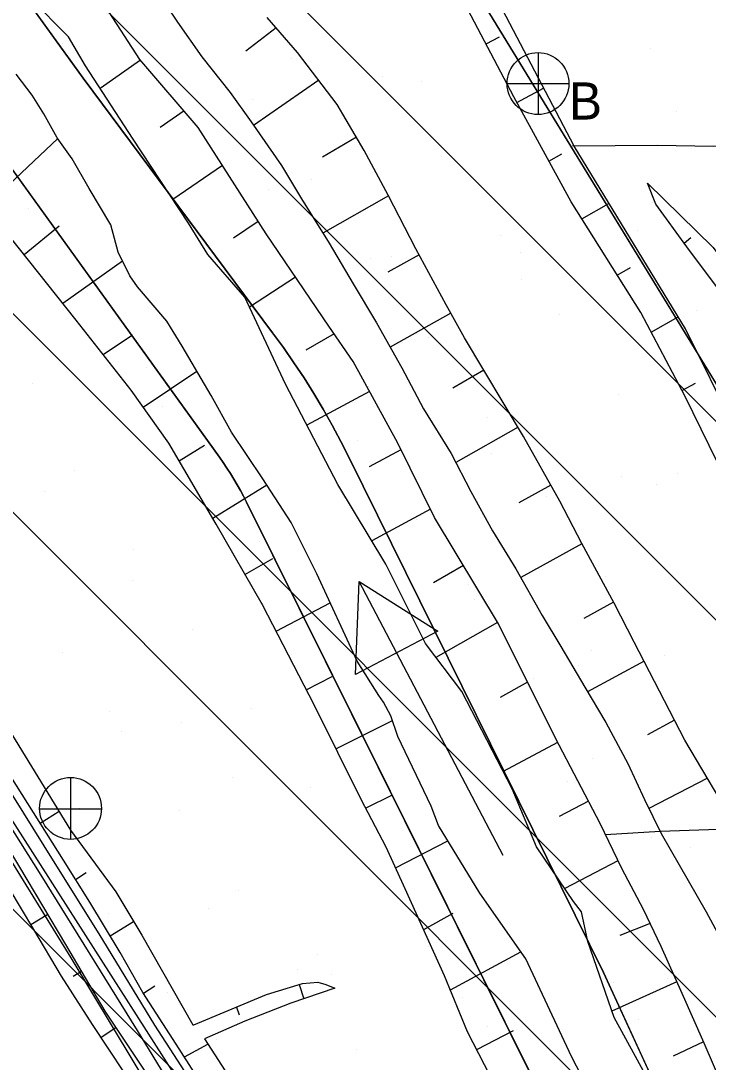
# Model space of a CAD drawing. Extents: x 417995 to 421451, y 4454518 to 4458015.
# Drawn here: x 421031.2 to 421108.9, y 4456083.1 to 4456200.9 of the extents above; entities that cross this region are included whole.
import ezdxf

# ---------------------------------------------------------------- set-up
doc = ezdxf.new("R2010")
doc.units = 0
for name, color, linetype in [('ADAKENARI', 7, 'Continuous'), ('Default', 7, 'Continuous'), ('Hid_Dere_Sulu_Yat_Gen', 7, 'Continuous'), ('PL_AYA_BOLGE_PARKI', 7, 'Continuous'), ('PL_AYA_PARK_DINLENME', 7, 'Continuous'), ('PL_TA_K_DERE', 7, 'Continuous'), ('S_Istikamet_Oku', 7, 'Continuous'), ('S_Rogar_Kapagi', 7, 'Continuous'), ('S_Rogar_Kapagi_Buski', 7, 'Continuous'), ('Sev_Sevalti', 7, 'Continuous'), ('Sev_Sevustu', 7, 'Continuous'), ('Sev_Tarama', 7, 'Continuous'), ('Sinir_itirazli_Mulkiyet', 7, 'Continuous'), ('Sinir_Tel_bir_taraf', 7, 'Continuous'), ('SN_TR_SIVILASMA', 7, 'Continuous'), ('TR_PARKALANI', 7, 'Continuous'), ('Yol_Toprak_Duz', 7, 'Continuous'), ('Yol_Toprak_Kesik', 7, 'Continuous')]:
    doc.layers.add(name, color=color, linetype=linetype)

# ---------------------------------------------------------------- blocks, each defined once
blk = doc.blocks.new('POINT_DISPLAY')
at = {"layer": 'Default'}
blk.add_line((0, 0), (0, 0), dxfattribs=at)

msp = doc.modelspace()

# ---------------------------------------------------------------- linework, layer by layer
at = {"layer": 'ADAKENARI'}
for p, q in [((420917.7, 4456473.63), (421125.1, 4456134.88)), ((421053.63, 4456151.54), (420943.98, 4456303.65)), ((420959.73, 4456303.08), (421038.21, 4456194.41)), ((421080.66, 4456031.58), (420960.94, 4456218.7)), ((421038.21, 4456194.41), (421059.65, 4456165.62)), ((421059.65, 4456165.62), (421060.87, 4456163.94)), ((421060.87, 4456163.94), (421062.06, 4456162.23)), ((421062.06, 4456162.23), (421063.2, 4456160.5)), ((421063.2, 4456160.5), (421064.3, 4456158.74)), ((421064.3, 4456158.74), (421065.37, 4456156.96)), ((421065.37, 4456156.96), (421066.39, 4456155.15)), ((421066.39, 4456155.15), (421067.37, 4456153.32)), ((421067.37, 4456153.32), (421068.32, 4456151.47)), ((421054.06, 4456150.93), (421053.63, 4456151.54)), ((421068.32, 4456151.47), (421097.08, 4456093.28)), ((421054.47, 4456150.32), (421054.06, 4456150.93)), ((421054.87, 4456149.69), (421054.47, 4456150.32)), ((421055.26, 4456149.06), (421054.87, 4456149.69)), ((421055.64, 4456148.42), (421055.26, 4456149.06)), ((421056, 4456147.78), (421055.64, 4456148.42)), ((421056.35, 4456147.12), (421056, 4456147.78)), ((421056.69, 4456146.46), (421056.35, 4456147.12)), ((421128.16, 4456002.78), (421056.69, 4456146.46)), ((421097.08, 4456093.28), (421123.49, 4456035.93))]:
    msp.add_line(p, q, dxfattribs=at)
at = {"layer": 'Hid_Dere_Sulu_Yat_Gen'}
for points in [[(421103.34, 4456078.94), (421098.27, 4456088.18), (421095.3, 4456096.78), (421094.59, 4456100.15), (421093.69, 4456101.29), (421089.5, 4456107.48), (421086.74, 4456114.05), (421081.05, 4456125.03), (421076.93, 4456130.47), (421072.47, 4456139.45), (421067.01, 4456148.44), (421061.1, 4456159.81), (421056.49, 4456169.64), (421052.33, 4456174.45), (421050.13, 4456177.99), (421043.78, 4456187.61), (421038.47, 4456195.8), (421036.55, 4456199.07), (421032.24, 4456203.5)], [(421097.4, 4456076.13), (421093.46, 4456083.78), (421088.28, 4456094.82), (421083.09, 4456102.26), (421078.42, 4456109.88), (421077.59, 4456112.07), (421073.82, 4456119.95), (421073.04, 4456122.28), (421072.21, 4456123.86), (421071.67, 4456124.59), (421069.22, 4456128.46), (421064.64, 4456138.34), (421061.73, 4456144.15), (421058.54, 4456149.11), (421054.99, 4456154.39), (421052.69, 4456158.5), (421049.42, 4456164.09), (421047.67, 4456166.91), (421044.35, 4456170.81), (421043.49, 4456172.05), (421042.19, 4456174.73), (421041.34, 4456177.81), (421038.91, 4456181.92), (421036.96, 4456185.27), (421035.28, 4456187.65), (421033.75, 4456190.36), (421032.44, 4456192.47), (421030.65, 4456194.86)]]:
    msp.add_lwpolyline(points, dxfattribs=at)
at = {"layer": 'PL_AYA_BOLGE_PARKI'}
msp.add_lwpolyline([(420862.75, 4456551.08), (420917.7, 4456473.63), (421125.1, 4456134.88)], dxfattribs=at)
at = {"layer": 'PL_AYA_PARK_DINLENME'}
for points in [[(421088.01, 4455998.87), (421080.33, 4456015.32), (421072.31, 4456031.61), (421063.94, 4456047.72), (421055.24, 4456063.65), (421046.21, 4456079.4), (421036.85, 4456094.95), (421036.85, 4456094.94), (420796.81, 4456484.25)], [(420917.7, 4456473.63), (421125.1, 4456134.88), (421134.31, 4456119.44), (421143.18, 4456103.81), (421151.7, 4456087.99), (421159.87, 4456071.98), (421167.68, 4456055.79), (421175.13, 4456039.43), (421182.22, 4456022.92), (421188.93, 4456006.25), (421195.28, 4455989.43)], [(420943.98, 4456303.65), (421053.63, 4456151.54), (421054.06, 4456150.93), (421054.47, 4456150.32), (421054.87, 4456149.69), (421055.26, 4456149.06), (421055.64, 4456148.42), (421056, 4456147.78), (421056.35, 4456147.12), (421056.69, 4456146.46), (421128.16, 4456002.78), (421151.46, 4455956.18)], [(421152.17, 4455978.57), (421123.49, 4456035.93), (421097.08, 4456093.28), (421068.32, 4456151.47), (421067.37, 4456153.32), (421066.39, 4456155.15), (421065.37, 4456156.96), (421064.3, 4456158.74), (421063.2, 4456160.5), (421062.06, 4456162.23), (421060.87, 4456163.94), (421059.65, 4456165.62), (421038.21, 4456194.41), (420959.73, 4456303.08)]]:
    msp.add_lwpolyline(points, dxfattribs=at)
at = {"layer": 'PL_TA_K_DERE'}
for points in [[(420943.98, 4456303.65), (421053.63, 4456151.54), (421054.06, 4456150.93), (421054.47, 4456150.32), (421054.87, 4456149.69), (421055.26, 4456149.06), (421055.64, 4456148.42), (421056, 4456147.78), (421056.35, 4456147.12), (421056.69, 4456146.46), (421128.16, 4456002.78), (421151.46, 4455956.18)], [(421152.17, 4455978.57), (421123.49, 4456035.93), (421097.08, 4456093.28), (421068.32, 4456151.47), (421067.37, 4456153.32), (421066.39, 4456155.15), (421065.37, 4456156.96), (421064.3, 4456158.74), (421063.2, 4456160.5), (421062.06, 4456162.23), (421060.87, 4456163.94), (421059.65, 4456165.62), (421038.21, 4456194.41), (420959.73, 4456303.08)]]:
    msp.add_lwpolyline(points, dxfattribs=at)
at = {"layer": 'S_Istikamet_Oku'}
for p, q in [((421069.03, 4456126.97), (421069.44, 4456137.47)), ((421085.73, 4456106.49), (421069.44, 4456137.47)), ((421069.44, 4456137.47), (421078.33, 4456131.86)), ((421078.33, 4456131.86), (421069.03, 4456126.97)), ((421078.13, 4456131.99), (421078.13, 4456131.99)), ((421078.13, 4456131.99), (421078.13, 4456131.99))]:
    msp.add_line(p, q, dxfattribs=at)
at = {"layer": 'S_Rogar_Kapagi'}
for p, q in [((421036.84, 4456108.31), (421036.84, 4456115.31)), ((421033.27, 4456111.77), (421040.27, 4456111.77))]:
    msp.add_line(p, q, dxfattribs=at)
msp.add_circle((421036.79, 4456111.83), 3.5, dxfattribs=at)
at = {"layer": 'S_Rogar_Kapagi_Buski'}
for p, q in [((421089.67, 4456197.29), (421089.67, 4456190.29)), ((421086.17, 4456193.79), (421093.17, 4456193.79))]:
    msp.add_line(p, q, dxfattribs=at)
msp.add_circle((421089.67, 4456193.79), 3.5, dxfattribs=at)
at = {"layer": 'Sev_Sevalti'}
for points in [[(421187.5, 4456114.49), (421152.1, 4456115.65), (421136.4, 4456115.89), (421133.91, 4456116.58), (421128.87, 4456123.93), (421123.11, 4456135.15), (421117.67, 4456144.85), (421111.98, 4456154.75), (421106.35, 4456166.06), (421093.76, 4456186.7), (421085.26, 4456202.89), (421080.76, 4456211.67), (421071.96, 4456227.21), (421061.34, 4456243.49), (421051.89, 4456256.28), (421041.66, 4456272.25), (421035.99, 4456281.59), (421027.71, 4456295.81), (421022.87, 4456306.93)], [(421046.26, 4456204.69), (421048.89, 4456200.72), (421051.63, 4456196.81), (421054.85, 4456192.76), (421057.22, 4456189.45), (421060.65, 4456184.54), (421062.93, 4456180.74), (421066.03, 4456175.73), (421068.76, 4456171.16), (421071.41, 4456166.73), (421074.28, 4456161.65), (421076.73, 4456157), (421079.84, 4456151.95), (421082.06, 4456147.65), (421084.51, 4456143.23), (421087.18, 4456138.9), (421090.14, 4456133.64), (421092.24, 4456130.12), (421094.96, 4456125.53), (421097.33, 4456121.54), (421099.82, 4456116.9), (421101.7, 4456112.85), (421103.59, 4456109.01), (421108.71, 4456100.12), (421112.96, 4456092.25)], [(421103.34, 4456078.94), (421098.27, 4456088.18), (421095.3, 4456096.78), (421094.59, 4456100.15), (421093.69, 4456101.29), (421089.5, 4456107.48), (421086.74, 4456114.05), (421081.05, 4456125.03), (421076.93, 4456130.47), (421072.47, 4456139.45), (421067.01, 4456148.44), (421061.1, 4456159.81), (421056.49, 4456169.64), (421052.33, 4456174.45), (421050.13, 4456177.99), (421043.78, 4456187.61), (421038.47, 4456195.8), (421036.55, 4456199.07), (421032.24, 4456203.5)], [(420981.53, 4456200.82), (420985.46, 4456194.46), (420989.57, 4456187.63), (420993.82, 4456179.59), (420997.48, 4456172.93), (421001.69, 4456166.45), (421005.49, 4456160.76), (421012.87, 4456149.79), (421016.12, 4456143.59), (421021.62, 4456134.26), (421027.94, 4456123.77), (421036.8, 4456109.38), (421041.9, 4456102.38), (421044.85, 4456097.48), (421050.63, 4456087.34)], [(421097.4, 4456076.13), (421093.46, 4456083.78), (421088.28, 4456094.82), (421083.09, 4456102.26), (421078.42, 4456109.88), (421077.59, 4456112.07), (421073.82, 4456119.95), (421073.04, 4456122.28), (421072.21, 4456123.86), (421071.67, 4456124.59), (421069.22, 4456128.46), (421064.64, 4456138.34), (421061.73, 4456144.15), (421058.54, 4456149.11), (421054.99, 4456154.39), (421052.69, 4456158.5), (421049.42, 4456164.09), (421047.67, 4456166.91), (421044.35, 4456170.81), (421043.49, 4456172.05), (421042.19, 4456174.73), (421041.34, 4456177.81), (421038.91, 4456181.92), (421036.96, 4456185.27), (421035.28, 4456187.65), (421033.75, 4456190.36), (421032.44, 4456192.47), (421030.65, 4456194.86)], [(421102.05, 4456182.51), (421109.49, 4456175.24), (421116.81, 4456165.26), (421123.12, 4456156.98), (421127.12, 4456148.55), (421131.6, 4456138.36), (421135.06, 4456129.81), (421137.23, 4456124.28), (421137.65, 4456121.8), (421137.29, 4456119.54)], [(421044.67, 4456079.27), (421039.28, 4456087.4), (421035.76, 4456092.85), (421032.63, 4456098.13), (421029.86, 4456102.8), (421024.55, 4456111.54), (421021.32, 4456117.19), (421017.79, 4456122.38), (421015.33, 4456126.41), (421012.17, 4456131.8), (421009.28, 4456136.48), (421006.12, 4456141.71), (421002.42, 4456146.74), (420999.46, 4456151.32), (420996.31, 4456156.29), (420993.34, 4456160.43), (420990.9, 4456164.01), (420989.26, 4456167.55), (420988.12, 4456170.4), (420988.01, 4456173.95)], [(421066.69, 4456091.51), (421061.7, 4456089.79), (421056.49, 4456087.76), (421051.94, 4456085.79), (421060.47, 4456072.59), (421065.96, 4456061.83), (421071.99, 4456051.11), (421077.47, 4456041.76), (421080.94, 4456036.49), (421083.95, 4456030.97), (421087.02, 4456024.17), (421089.21, 4456019.52), (421091.82, 4456013.25), (421094.71, 4456007.22), (421097.85, 4456000.22)]]:
    msp.add_lwpolyline(points, dxfattribs=at)
at = {"layer": 'Sev_Sevustu'}
for points in [[(421204.78, 4456110.51), (421178.81, 4456110.45), (421142.69, 4456111.53), (421132.67, 4456112.57), (421129.35, 4456114.57), (421124.09, 4456123.04), (421119.43, 4456131.97), (421113.53, 4456143.71), (421106.31, 4456158.4), (421101.3, 4456167.9), (421093.41, 4456180.42), (421086.92, 4456192.3), (421079.18, 4456207.06), (421074.43, 4456214.66), (421067.21, 4456226.87), (421052.29, 4456249.7), (421039.34, 4456268.38), (421028.21, 4456288.78), (421016.29, 4456308.87)], [(421111.41, 4456078.46), (421108.48, 4456085.27), (421105.97, 4456090.91), (421103.61, 4456096.23), (421101.6, 4456100.4), (421099.14, 4456105.02), (421096.69, 4456110.11), (421091.64, 4456119.76), (421085.2, 4456132.69), (421077.97, 4456144.74), (421073.8, 4456153.14), (421068.77, 4456162.35), (421066, 4456166.36), (421058.91, 4456176.79), (421051.23, 4456188.83), (421044.62, 4456196.52), (421039.43, 4456204.59)], [(421086.19, 4456077.85), (421081.71, 4456086.57), (421079.11, 4456092.9), (421074.66, 4456102.72), (421072.49, 4456107.45), (421069.67, 4456112.83), (421064.37, 4456123.46), (421058.5, 4456134.84), (421053.27, 4456143.98), (421047.92, 4456153.11), (421043.64, 4456159.11), (421037.44, 4456167.05), (421029.85, 4456176.56), (421023.05, 4456185.41), (421017.09, 4456193.75), (421011.16, 4456201.55)], [(421128.64, 4456079.86), (421124.91, 4456085.93), (421122.05, 4456091.5), (421119.64, 4456096.7), (421116.83, 4456101.25), (421112.26, 4456109.45), (421106.28, 4456119.54), (421100.56, 4456130.62), (421098.28, 4456135.05), (421094.62, 4456141.79), (421092.15, 4456146.58), (421088.02, 4456153.89), (421081.35, 4456165.03), (421079.28, 4456168.77), (421075.84, 4456175.09), (421072.72, 4456181.17), (421070.02, 4456186.21), (421066.96, 4456191.41), (421062.48, 4456197.31), (421059.03, 4456201.27)], [(421051.69, 4456080.59), (421048.74, 4456085.19), (421044.97, 4456091.02), (421042.39, 4456095.55), (421038.99, 4456101.22), (421035.99, 4456105.97), (421030.05, 4456115.45), (421024.53, 4456124.46), (421019.09, 4456133.26), (421013.33, 4456142.6), (421006.93, 4456152.03), (421003.96, 4456157.03), (421000.32, 4456162.58), (420996.7, 4456168.43), (420993.06, 4456174.54), (420988.87, 4456181.75), (420986.12, 4456186.28), (420983.68, 4456190.81)], [(421137.29, 4456119.54), (421136.91, 4456120.22), (421128.04, 4456138.64), (421121.14, 4456152.73), (421116.25, 4456161.63), (421111.33, 4456168.89), (421106.49, 4456175.34), (421102.99, 4456180.14), (421102.05, 4456182.51)], [(420988.01, 4456173.95), (420991.36, 4456168.74), (421000.24, 4456154.63), (421004.59, 4456147.53), (421010.2, 4456138.7), (421014.78, 4456131.04), (421020.69, 4456121.52), (421025.78, 4456113.82), (421031, 4456105.19), (421036.22, 4456096.46), (421040.66, 4456088.91), (421045.95, 4456081), (421051.02, 4456073.3), (421056.06, 4456064.85), (421060.11, 4456057.41), (421064.01, 4456049.76), (421067, 4456044.83), (421069.38, 4456040.7), (421070.8, 4456038.52), (421072.45, 4456035.91)], [(421050.63, 4456087.34), (421050.74, 4456087.37), (421058.97, 4456090.79), (421063.04, 4456092.04), (421064.77, 4456092.17), (421065.65, 4456091.92), (421066.69, 4456091.51)]]:
    msp.add_lwpolyline(points, dxfattribs=at)
at = {"layer": 'Sev_Tarama'}
for p, q in [((421060.05, 4456200.1), (421056.63, 4456197.46)), ((421083.79, 4456198.27), (421085.31, 4456199.09)), ((421044.7, 4456196.42), (421040.15, 4456193.22)), ((421064.87, 4456194.16), (421057.5, 4456189.05)), ((421087.28, 4456191.64), (421090.31, 4456193.26)), ((421049.63, 4456190.69), (421046.93, 4456188.81)), ((421069.12, 4456187.74), (421065.3, 4456185.45)), ((421027.25, 4456179.95), (421035.35, 4456187.56)), ((421090.89, 4456185.03), (421092.35, 4456185.83)), ((421053.97, 4456184.53), (421048.35, 4456180.69)), ((421102.19, 4456182.15), (421102.31, 4456182.25)), ((421072.75, 4456181.1), (421065.32, 4456176.88)), ((421094.62, 4456178.5), (421097.7, 4456180.23)), ((421031.54, 4456174.45), (421035.52, 4456177.69)), ((421058.02, 4456178.18), (421055.21, 4456176.29)), ((421106.19, 4456175.76), (421106.95, 4456176.37)), ((421035.92, 4456168.96), (421042.67, 4456173.73)), ((421076.21, 4456174.41), (421072.69, 4456172.45)), ((421098.64, 4456172.13), (421100.12, 4456172.98)), ((421062.25, 4456171.88), (421057.02, 4456168.51)), ((421079.8, 4456167.84), (421072.96, 4456163.99)), ((421102.47, 4456165.68), (421105.51, 4456167.43)), ((421040.48, 4456163.15), (421043.78, 4456165.38)), ((421066.6, 4456165.5), (421063.39, 4456163.64)), ((421045.02, 4456157.18), (421051.07, 4456161.28)), ((421083.53, 4456161.38), (421080.05, 4456159.35)), ((421105.95, 4456159.09), (421107.47, 4456159.92)), ((421070.62, 4456158.96), (421063.52, 4456155.16)), ((421087.41, 4456154.92), (421080.37, 4456150.93)), ((421049.09, 4456151.12), (421051.96, 4456152.89)), ((421074.17, 4456152.39), (421070.58, 4456150.44)), ((421052.87, 4456144.66), (421058.99, 4456148.4)), ((421091.13, 4456148.39), (421087.51, 4456146.37)), ((421077.51, 4456145.67), (421070.88, 4456142.07)), ((421094.64, 4456141.75), (421087.72, 4456137.93)), ((421056.52, 4456138.29), (421059.69, 4456140.09)), ((421081.25, 4456139.28), (421077.86, 4456137.35)), ((421060.04, 4456131.86), (421066.16, 4456135.06)), ((421098.22, 4456135.16), (421094.84, 4456133.29)), ((421085.1, 4456132.86), (421078.13, 4456128.88)), ((421101.67, 4456128.47), (421095.26, 4456125.02)), ((421063.45, 4456125.24), (421066.4, 4456126.74)), ((421088.48, 4456126.11), (421085.39, 4456124.37)), ((421105.11, 4456121.8), (421102.04, 4456120.15)), ((421066.81, 4456118.57), (421073.21, 4456121.77)), ((421091.87, 4456119.3), (421085.72, 4456116.02)), ((421108.83, 4456115.24), (421102.21, 4456111.82)), ((421070.16, 4456111.87), (421073.2, 4456113.38)), ((421095.37, 4456112.63), (421092.08, 4456110.9)), ((421033.36, 4456110.17), (421035.49, 4456111.51)), ((421073.56, 4456105.1), (421079.47, 4456108.17)), ((421098.71, 4456105.92), (421092.69, 4456102.76)), ((421037.35, 4456103.81), (421038.55, 4456104.58)), ((421034.21, 4456099.82), (421032.3, 4456098.68)), ((421076.74, 4456098.13), (421080.06, 4456099.98)), ((421041.26, 4456097.44), (421043.91, 4456099.04)), ((421102.36, 4456098.82), (421098.94, 4456097.47)), ((421079.77, 4456091.3), (421087.71, 4456095.63)), ((421038.02, 4456093.4), (421037.09, 4456092.81)), ((421045.03, 4456090.93), (421046.33, 4456091.76)), ((421062.67, 4456091.93), (421063.18, 4456090.3)), ((421105.38, 4456092.22), (421098.02, 4456088.9)), ((421055.56, 4456089.37), (421055.88, 4456088.5)), ((421041.92, 4456087.03), (421040.25, 4456085.93)), ((421082.74, 4456084.56), (421086.91, 4456086.7)), ((421108.4, 4456085.45), (421104.97, 4456083.83)), ((421049.67, 4456083.74), (421052.32, 4456085.19))]:
    msp.add_line(p, q, dxfattribs=at)
at = {"layer": 'Sinir_itirazli_Mulkiyet'}
msp.add_lwpolyline([(421249.69, 4456183.87), (421233.27, 4456184.05), (421210.62, 4456184.74), (421188.98, 4456185.53), (421155.63, 4456186.64), (421142.24, 4456187), (421131.24, 4456186.86), (421120.32, 4456186.91), (421109.49, 4456186.69), (421103.21, 4456186.79), (421093.59, 4456186.7)], dxfattribs=at)
at = {"layer": 'Sinir_Tel_bir_taraf'}
msp.add_lwpolyline([(421256.37, 4456110.32), (421252.18, 4456109.74), (421236.3, 4456108.89), (421216.23, 4456108.27), (421202.77, 4456108.32), (421189.82, 4456108.77), (421183.02, 4456108.72), (421164.1, 4456109.39), (421143.49, 4456109.74), (421130.19, 4456109.82), (421121.48, 4456109.59), (421112.23, 4456109.51), (421103.5, 4456109.21), (421097.29, 4456108.86)], dxfattribs=at)
at = {"layer": 'SN_TR_SIVILASMA'}
for p, q in [((421276.73, 4455988.66), (419957.49, 4457307.89)), ((421276.49, 4455966.44), (419971.97, 4457270.96)), ((421276.03, 4455922), (420004.05, 4457193.98)), ((421275.8, 4455899.78), (420015.35, 4457160.22)), ((421275.33, 4455855.34), (420037.81, 4457092.87))]:
    msp.add_line(p, q, dxfattribs=at)
at = {"layer": 'Yol_Toprak_Duz'}
msp.add_lwpolyline([(420978.47, 4456193.19), (420983.9, 4456183.28), (420994.38, 4456166.59), (421004.61, 4456150.21), (421012.12, 4456138.8), (421023.54, 4456119.93), (421033.41, 4456104.27), (421044.32, 4456086.73), (421054.95, 4456069.32), (421061.73, 4456056.83), (421068.7, 4456043.91), (421074.48, 4456033), (421079.07, 4456024.38), (421083.45, 4456014.76), (421086.1, 4456009.07), (421091.58, 4455998.12)], dxfattribs=at)
at = {"layer": 'Yol_Toprak_Kesik'}
msp.add_lwpolyline([(421093.06, 4456000.28), (421089.08, 4456008.05), (421086.45, 4456013.42), (421083.34, 4456020.5), (421079.91, 4456028.18), (421077.54, 4456032.9), (421072.11, 4456042.62), (421066, 4456053.79), (421060.59, 4456063.7), (421056.42, 4456071.36), (421051.88, 4456078.78), (421046.33, 4456087.32), (421040.03, 4456097.63), (421034.88, 4456105.92), (421029.22, 4456114.99), (421022.98, 4456125.05), (421017.13, 4456134.66), (421011.04, 4456143.99), (421005.73, 4456152.29), (421000.33, 4456160.99), (420995.01, 4456169.33), (420990.39, 4456177.36), (420986.81, 4456183.28), (420982.12, 4456191.98)], dxfattribs=at)

# ---------------------------------------------------------------- block references
at = {"layer": 'TR_PARKALANI', "xscale": 0.1, "yscale": 0.10000000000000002}
for p in [(421035.91, 4456198.34), (421086.89, 4456197.18), (421102.35, 4456197.71), (421061.77, 4456196.57), (421072.12, 4456194.57), (421076.54, 4456193.97), (421057.35, 4456191.97), (421105.39, 4456190.67), (421042.57, 4456189.36), (421078.78, 4456185.59), (421094.24, 4456186.13), (421064.01, 4456182.99), (421059.17, 4456181.8), (421032.08, 4456179.62), (421049.23, 4456180.38), (421063.33, 4456180.38), (421102.64, 4456180.29), (421100.9, 4456177.15), (421085.44, 4456176.61), (421070.67, 4456174.01), (421073.07, 4456174.27), (421087.67, 4456174.7), (421055.89, 4456171.4), (421087.84, 4456171.67), (421038.74, 4456170.64), (421107.56, 4456168.17), (421092.1, 4456167.63), (421077.33, 4456165.03), (421062.56, 4456162.42), (421045.4, 4456161.66), (421032.46, 4456159.91), (421070.47, 4456159.5), (421098.76, 4456158.65), (421047.23, 4456157.3), (421083.99, 4456156.05), (421078.78, 4456154.18), (421052.06, 4456152.68), (421069.22, 4456153.44), (421084.37, 4456151.97), (421037.29, 4456150.07), (421099.14, 4456149.37), (421105.42, 4456149.67), (421033.84, 4456147.7), (421103.13, 4456148.5), (421090.65, 4456147.07), (421075.88, 4456144.46), (421058.19, 4456142.02), (421043.95, 4456141.09), (421043.76, 4456137.61), (421081.77, 4456137.2), (421097.31, 4456138.09), (421058.53, 4456135), (421082.54, 4456135.48), (421050.61, 4456132.11), (421035.84, 4456129.51), (421095.67, 4456129.67), (421103.97, 4456129.11), (421094.23, 4456127.99), (421089.2, 4456126.5), (421057.27, 4456123.13), (421041.15, 4456122.84), (421049.3, 4456121.51), (421042.5, 4456120.53), (421095.86, 4456117.52), (421055.06, 4456115.31), (421093.06, 4456114.9), (421063.93, 4456114.15), (421069.83, 4456112.7), (421037.81, 4456111.87), (421049.16, 4456111.55), (421034.39, 4456108.94), (421102.52, 4456108.55), (421106.97, 4456107.37), (421070.59, 4456105.17), (421055.82, 4456102.57), (421041.05, 4456099.96), (421052.45, 4456100.53), (421077.25, 4456096.19), (421064.75, 4456095.31), (421062.48, 4456093.59), (421066.36, 4456093.01), (421104.36, 4456092.6), (421098.2, 4456092.15), (421047.71, 4456090.98), (421081.13, 4456090.4), (421101.07, 4456087.98), (421083.91, 4456087.21), (421053.26, 4456085.67), (421069.14, 4456084.61)]:
    msp.add_blockref('POINT_DISPLAY', p, dxfattribs=at)

# ---------------------------------------------------------------- texts
at = {"layer": 'S_Rogar_Kapagi_Buski'}
msp.add_text('B', height=4.2, dxfattribs=at).set_placement((421093.17, 4456189.72))

doc.saveas('drawing.dxf')
